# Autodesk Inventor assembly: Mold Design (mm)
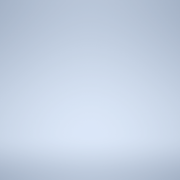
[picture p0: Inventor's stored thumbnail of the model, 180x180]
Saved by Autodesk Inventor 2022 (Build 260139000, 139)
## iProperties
Created: 2002-07
Part Number: Mold Design (mm)
Document SubType Name: Assembly
Control State: 0
Master: False
Checked Out: False
Shininess: 64.0
Length Units: 11269
Angle Units: 11279
Time Units: 11290
Mass Units: 11283
Length Display Precision: 3
Angle Display Precision: 2
Compacted: True
Density: 0.0
Volumn: 0.0
Area: 0.0
PropertySet Name: Model Information
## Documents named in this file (1)
- C:\Users\ENU\Desktop\New folder for ita\Mold Design (mm).iam
